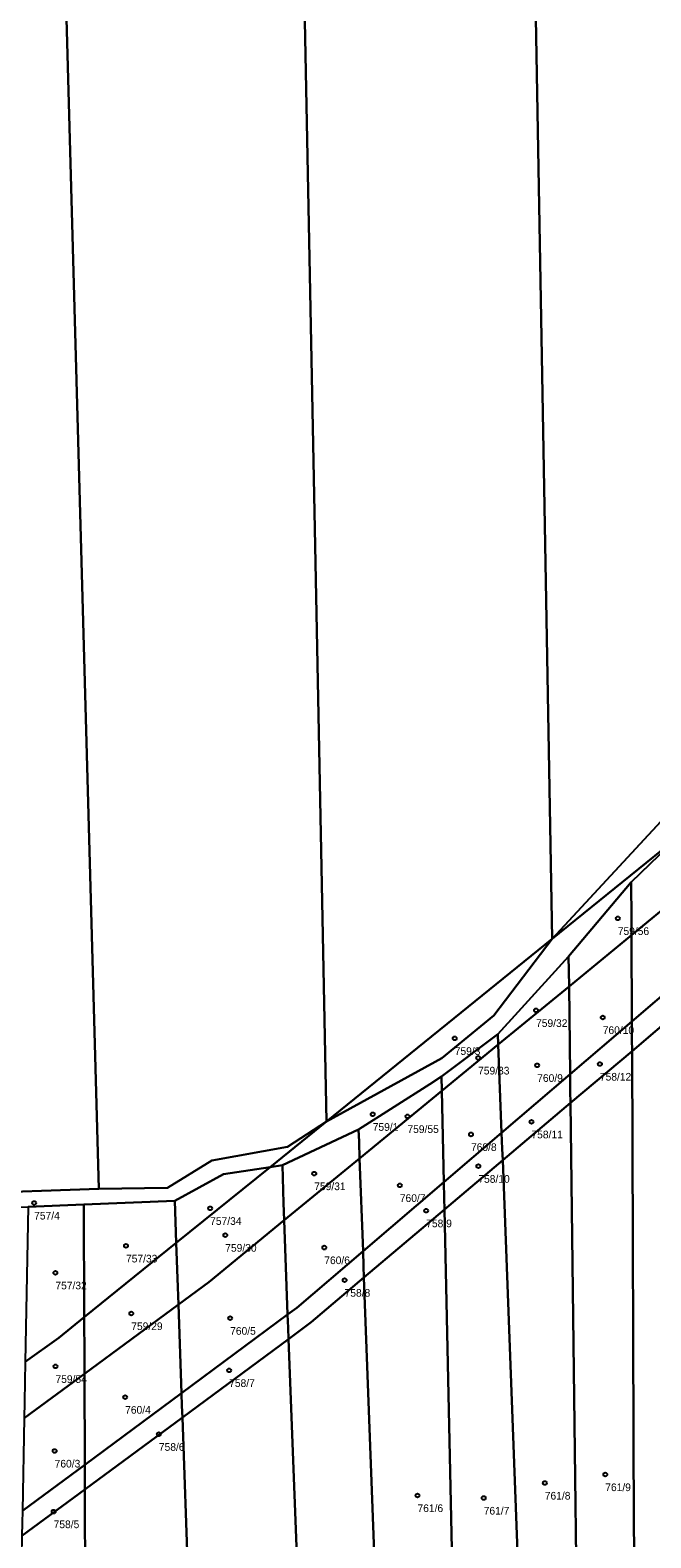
# Model space of a CAD drawing. Extents: x -587171 to -555306, y -1167727 to -1074732.
# Drawn here: x -586119 to -586038.1, y -1165235.6 to -1165038.9 of the extents above; entities that cross this region are included whole.
import ezdxf

# ---------------------------------------------------------------- set-up
doc = ezdxf.new("R2010")
doc.units = 0
doc.layers.add('Definiční body', color=7, linetype='Continuous')
doc.layers.add('Polygon parcely', color=7, linetype='Continuous')

msp = doc.modelspace()

# ---------------------------------------------------------------- linework, layer by layer
at = {"layer": 'Definiční body'}
for centre in [(-586042.38, -1165154.78), (-586053.04, -1165166.78), (-586044.34, -1165167.7), (-586063.65, -1165170.43), (-586060.6, -1165172.98), (-586052.89, -1165173.95), (-586044.71, -1165173.78), (-586074.35, -1165180.33), (-586069.82, -1165180.61), (-586053.64, -1165181.31), (-586061.53, -1165182.96), (-586060.57, -1165187.11), (-586081.98, -1165188.07), (-586070.81, -1165189.61), (-586118.52, -1165191.9), (-586095.56, -1165192.6), (-586067.37, -1165192.91), (-586093.59, -1165196.1), (-586106.54, -1165197.5), (-586080.67, -1165197.72), (-586115.75, -1165201.01), (-586078.02, -1165201.97), (-586105.85, -1165206.32), (-586092.95, -1165206.93), (-586115.74, -1165213.22), (-586093.08, -1165213.74), (-586106.65, -1165217.23), (-586102.25, -1165222.07), (-586115.85, -1165224.25), (-586051.9, -1165228.43), (-586044.01, -1165227.33), (-586068.51, -1165230.06), (-586059.87, -1165230.39), (-586115.98, -1165232.16)]:
    msp.add_circle(centre, 0.25, dxfattribs=at)
at = {"layer": 'Polygon parcely'}
for points in [[(-586116.67, -1164860.69), (-586141.88, -1164843.35), (-586141.97, -1164999.93), (-586142.35, -1165111.58), (-586138.88, -1165157.23), (-586141.44, -1165187.79), (-586127.57, -1165190.65), (-586110.07, -1165190.07), (-586114.84, -1165018.5)], [(-586086.33, -1164881.61), (-586116.67, -1164860.69), (-586114.84, -1165018.5), (-586110.07, -1165190.07), (-586101.11, -1165189.91), (-586095.36, -1165186.37), (-586085.49, -1165184.57), (-586080.4, -1165181.26), (-586083.75, -1165011.16)], [(-586050.93, -1165157.45), (-586053.49, -1165012.75), (-586054.54, -1164903.67), (-586086.33, -1164881.61), (-586083.75, -1165011.16), (-586080.4, -1165181.26)], [(-585991.62, -1164946.53), (-586054.54, -1164903.67), (-586053.49, -1165012.75), (-586050.93, -1165157.45), (-586035.13, -1165140.36), (-586004.57, -1165115.05), (-585993.09, -1165103.37)], [(-585930.21, -1165051.41), (-585914.04, -1165042.8), (-585907.32, -1165041.42), (-585904.72, -1165039.32), (-585908.87, -1165039.46), (-585914.37, -1165040.86), (-585930.15, -1165049.07), (-585944.13, -1165058.5), (-585964.22, -1165077.17), (-585979.78, -1165091.21), (-585993.09, -1165103.37), (-586004.57, -1165115.05), (-586035.13, -1165140.36), (-586050.93, -1165157.45), (-586034.57, -1165144.23), (-586026.6, -1165135.8), (-586014.68, -1165125.74), (-586002.99, -1165116.35), (-585996.14, -1165109.88), (-585986.39, -1165100), (-585963.41, -1165079.23), (-585946.64, -1165063.37)], [(-586086.14, -1165186.99), (-586076.2, -1165182.3), (-586066.92, -1165176.4), (-586065.37, -1165175.41), (-586058.02, -1165169.9), (-586055.37, -1165166.98), (-586048.79, -1165159.73), (-586040.62, -1165150.04), (-586034.57, -1165144.23), (-586050.93, -1165157.45), (-586058.53, -1165167.45), (-586065.33, -1165173.02), (-586080.4, -1165181.26), (-586087.75, -1165187.23)], [(-586034.44, -1165151.91), (-586034.47, -1165149.95), (-586034.57, -1165144.23), (-586040.62, -1165150.04), (-586040.6, -1165154.94), (-586040.59, -1165156.96)], [(-586040.59, -1165156.96), (-586040.6, -1165154.94), (-586040.62, -1165150.04), (-586048.79, -1165159.73), (-586048.77, -1165161.6), (-586048.74, -1165163.65)], [(-586034.25, -1165162.84), (-586034.44, -1165151.91), (-586040.59, -1165156.96), (-586040.54, -1165168.21)], [(-586050.93, -1165157.45), (-586080.4, -1165181.26), (-586065.33, -1165173.02), (-586058.53, -1165167.45)], [(-586040.54, -1165168.21), (-586040.59, -1165156.96), (-586048.74, -1165163.65), (-586048.6, -1165175.1)], [(-586048.77, -1165161.6), (-586048.79, -1165159.73), (-586055.37, -1165166.98), (-586058.02, -1165169.9), (-586057.97, -1165171.23), (-586048.74, -1165163.65)], [(-586040.52, -1165172.08), (-586034.18, -1165166.72), (-586034.21, -1165165.21), (-586034.25, -1165162.84), (-586040.54, -1165168.21), (-586040.53, -1165170.55)], [(-586048.6, -1165175.1), (-586048.74, -1165163.65), (-586057.97, -1165171.23), (-586057.53, -1165182.74)], [(-586033.79, -1165190.21), (-586034.18, -1165166.72), (-586040.52, -1165172.08), (-586040.27, -1165234.18), (-586039.3, -1165290.74), (-586031.18, -1165294.22), (-586032.77, -1165250.56), (-586036.34, -1165247.72), (-586035.46, -1165191.62)], [(-586040.52, -1165172.08), (-586040.53, -1165170.55), (-586040.54, -1165168.21), (-586048.6, -1165175.1), (-586048.57, -1165177.35), (-586048.55, -1165178.86)], [(-586065.33, -1165177.27), (-586057.97, -1165171.23), (-586058.02, -1165169.9), (-586065.37, -1165175.41)], [(-586057.53, -1165182.74), (-586057.97, -1165171.23), (-586065.33, -1165177.27), (-586065.07, -1165189.18)], [(-586039.3, -1165290.74), (-586040.27, -1165234.18), (-586040.52, -1165172.08), (-586048.55, -1165178.86), (-586047.22, -1165287.1), (-586043.25, -1165289.05)], [(-586057.39, -1165186.33), (-586048.55, -1165178.86), (-586048.57, -1165177.35), (-586048.6, -1165175.1), (-586057.53, -1165182.74), (-586057.45, -1165184.86)], [(-586065.33, -1165177.27), (-586065.37, -1165175.41), (-586066.92, -1165176.4), (-586076.2, -1165182.3), (-586076.14, -1165183.91), (-586076.06, -1165186.08)], [(-586065.07, -1165189.18), (-586065.33, -1165177.27), (-586076.06, -1165186.08), (-586075.61, -1165198.19)], [(-586047.22, -1165287.1), (-586048.55, -1165178.86), (-586057.39, -1165186.33), (-586053.71, -1165283.92)], [(-586127.08, -1165192.68), (-586119.3, -1165192.4), (-586112.03, -1165192.12), (-586100.17, -1165191.63), (-586093.81, -1165188.14), (-586087.75, -1165187.23), (-586080.4, -1165181.26), (-586085.49, -1165184.57), (-586095.36, -1165186.37), (-586101.11, -1165189.91), (-586110.07, -1165190.07), (-586127.57, -1165190.65), (-586141.44, -1165187.79), (-586142.57, -1165187.58), (-586142.56, -1165190.18)], [(-586076.06, -1165186.08), (-586076.14, -1165183.91), (-586076.2, -1165182.3), (-586086.14, -1165186.99), (-586085.97, -1165191.92), (-586085.89, -1165194.15)], [(-586064.99, -1165192.75), (-586057.39, -1165186.33), (-586057.45, -1165184.86), (-586057.53, -1165182.74), (-586065.07, -1165189.18), (-586065.02, -1165191.26)], [(-586095.74, -1165202.24), (-586085.89, -1165194.15), (-586085.97, -1165191.92), (-586086.14, -1165186.99), (-586087.75, -1165187.23), (-586099.98, -1165197.12), (-586099.78, -1165202.88), (-586099.7, -1165205.16)], [(-586075.61, -1165198.19), (-586076.06, -1165186.08), (-586085.89, -1165194.15), (-586085.46, -1165206.47), (-586084.24, -1165205.57)], [(-586057.39, -1165186.33), (-586064.99, -1165192.75), (-586063.1, -1165279.31), (-586053.71, -1165283.92)], [(-586087.75, -1165187.23), (-586093.81, -1165188.14), (-586100.17, -1165191.63), (-586099.98, -1165197.12)], [(-586064.99, -1165192.75), (-586065.02, -1165191.26), (-586065.07, -1165189.18), (-586075.61, -1165198.19), (-586075.54, -1165200.15), (-586075.49, -1165201.63)], [(-586111.98, -1165206.82), (-586112.03, -1165192.12), (-586119.3, -1165192.4), (-586119.68, -1165212.62), (-586115.29, -1165209.49)], [(-586099.98, -1165197.12), (-586100.17, -1165191.63), (-586112.03, -1165192.12), (-586111.98, -1165206.82)], [(-586063.1, -1165279.31), (-586064.99, -1165192.75), (-586075.49, -1165201.63), (-586072.78, -1165274.55)], [(-586085.46, -1165206.47), (-586085.89, -1165194.15), (-586095.74, -1165202.24), (-586099.7, -1165205.16), (-586099.3, -1165216.71)], [(-586111.95, -1165214.18), (-586099.7, -1165205.16), (-586099.78, -1165202.88), (-586099.98, -1165197.12), (-586111.98, -1165206.82), (-586111.96, -1165211.94)], [(-586085.35, -1165209.65), (-586082.38, -1165207.46), (-586075.49, -1165201.63), (-586075.54, -1165200.15), (-586075.61, -1165198.19), (-586084.24, -1165205.57), (-586085.46, -1165206.47), (-586085.4, -1165208.21)], [(-586072.78, -1165274.55), (-586075.49, -1165201.63), (-586082.38, -1165207.46), (-586085.35, -1165209.65), (-586083.03, -1165269.44), (-586079.8, -1165271.1)], [(-586099.3, -1165216.71), (-586099.7, -1165205.16), (-586111.95, -1165214.18), (-586111.92, -1165226.05)], [(-586099.3, -1165216.71), (-586099.24, -1165218.35), (-586099.19, -1165219.88), (-586085.35, -1165209.65), (-586085.4, -1165208.21), (-586085.46, -1165206.47)], [(-586111.95, -1165214.18), (-586111.96, -1165211.94), (-586111.98, -1165206.82), (-586115.29, -1165209.49), (-586119.68, -1165212.62), (-586119.78, -1165217.83), (-586119.82, -1165219.97)], [(-586083.03, -1165269.44), (-586085.35, -1165209.65), (-586099.19, -1165219.88), (-586097.7, -1165262.31)], [(-586111.92, -1165226.05), (-586111.95, -1165214.18), (-586119.82, -1165219.97), (-586120.05, -1165232.07)], [(-586099.19, -1165219.88), (-586099.24, -1165218.35), (-586099.3, -1165216.71), (-586111.92, -1165226.05), (-586111.92, -1165227.63), (-586111.91, -1165229.28)], [(-586097.7, -1165262.31), (-586099.19, -1165219.88), (-586111.91, -1165229.28), (-586111.83, -1165255.36)], [(-586111.91, -1165229.28), (-586111.92, -1165227.63), (-586111.92, -1165226.05), (-586120.05, -1165232.07), (-586120.08, -1165233.61), (-586120.11, -1165235.33)], [(-586111.83, -1165255.36), (-586111.91, -1165229.28), (-586120.11, -1165235.33), (-586120.4, -1165251.15)]]:
    msp.add_lwpolyline(points, close=True, dxfattribs=at)

# ---------------------------------------------------------------- texts
at = {"layer": 'Definiční body'}
for s, p in [('759/56', (-586042.38, -1165156.94)), ('759/32', (-586053.04, -1165168.94)), ('760/10', (-586044.34, -1165169.86)), ('759/3', (-586063.65, -1165172.59)), ('759/33', (-586060.6, -1165175.14)), ('760/9', (-586052.89, -1165176.11)), ('758/12', (-586044.71, -1165175.94)), ('759/1', (-586074.35, -1165182.49)), ('759/55', (-586069.82, -1165182.77)), ('758/11', (-586053.64, -1165183.47)), ('760/8', (-586061.53, -1165185.12)), ('758/10', (-586060.57, -1165189.27)), ('759/31', (-586081.98, -1165190.23)), ('760/7', (-586070.81, -1165191.77)), ('757/4', (-586118.52, -1165194.06)), ('757/34', (-586095.56, -1165194.76)), ('758/9', (-586067.37, -1165195.07)), ('757/33', (-586106.54, -1165199.66)), ('759/30', (-586093.59, -1165198.26)), ('760/6', (-586080.67, -1165199.88)), ('757/32', (-586115.75, -1165203.17)), ('758/8', (-586078.02, -1165204.13)), ('759/29', (-586105.85, -1165208.48)), ('760/5', (-586092.95, -1165209.09)), ('759/54', (-586115.74, -1165215.38)), ('758/7', (-586093.08, -1165215.9)), ('760/4', (-586106.65, -1165219.39)), ('758/6', (-586102.25, -1165224.23)), ('760/3', (-586115.85, -1165226.41)), ('761/9', (-586044.01, -1165229.49)), ('761/8', (-586051.9, -1165230.59)), ('761/6', (-586068.51, -1165232.22)), ('761/7', (-586059.87, -1165232.55)), ('758/5', (-586115.98, -1165234.32))]:
    msp.add_text(s, height=1, dxfattribs=at).set_placement(p)

doc.saveas('drawing.dxf')
